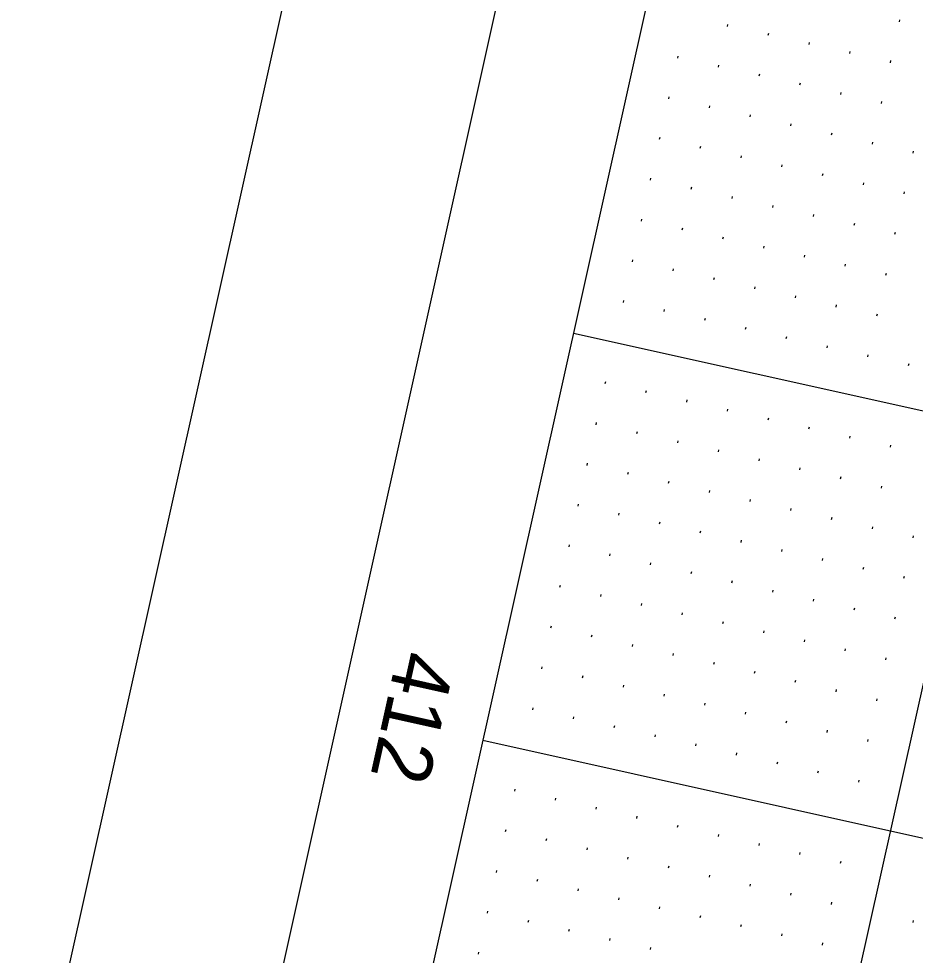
# Model space of a CAD drawing. Extents: x 2149268 to 2150830, y 142155 to 144285.
# Drawn here: x 2149611.6 to 2149719, y 143717.6 to 143829.9 of the extents above; entities that cross this region are included whole.
import ezdxf

# ---------------------------------------------------------------- set-up
doc = ezdxf.new("R2010")
doc.units = 0
for name, color, linetype in [('SHT_Plan_Profile_Sheet_Sta_Txt', 7, 'Continuous'), ('SHT_Plot_Shape_Half', 7, 'Continuous'), ('SHT_Profile_Grid_Major', 7, 'Continuous'), ('SHT_Profile_Grid_Minor', 7, 'Continuous'), ('SHT_Sheet_Border', 7, 'Continuous')]:
    doc.layers.add(name, color=color, linetype=linetype)

msp = doc.modelspace()

# ---------------------------------------------------------------- linework, layer by layer
at = {"layer": 'SHT_Plot_Shape_Half'}
msp.add_lwpolyline([(2150772.24, 143840.86), (2150403.25, 142181.39), (2149329.47, 142420.15), (2149698.47, 144079.62)], close=True, dxfattribs=at)
at = {"layer": 'SHT_Profile_Grid_Major'}
for p, q in [((2149767.6, 143964.37), (2149425.74, 142426.92)), ((2149678.09, 143792.19), (2150166.17, 143683.67)), ((2149667.24, 143743.39), (2150155.32, 143634.86))]:
    msp.add_line(p, q, dxfattribs=at)
at = {"layer": 'SHT_Profile_Grid_Minor'}
for p, q in [((2149696.56, 143829.19), (2149696.51, 143828.95)), ((2149717.17, 143829.73), (2149717.12, 143829.49)), ((2149701.44, 143828.11), (2149701.39, 143827.86)), ((2149706.32, 143827.02), (2149706.27, 143826.78)), ((2149711.21, 143825.94), (2149711.15, 143825.69)), ((2149690.6, 143825.4), (2149690.54, 143825.15)), ((2149695.48, 143824.31), (2149695.42, 143824.07)), ((2149716.09, 143824.85), (2149716.03, 143824.61)), ((2149700.36, 143823.23), (2149700.3, 143822.98)), ((2149705.24, 143822.14), (2149705.19, 143821.9)), ((2149710.12, 143821.05), (2149710.07, 143820.81)), ((2149689.51, 143820.52), (2149689.46, 143820.27)), ((2149715, 143819.97), (2149714.95, 143819.73)), ((2149694.39, 143819.43), (2149694.34, 143819.19)), ((2149699.27, 143818.34), (2149699.22, 143818.1)), ((2149704.15, 143817.26), (2149704.1, 143817.02)), ((2149688.43, 143815.63), (2149688.37, 143815.39)), ((2149709.03, 143816.17), (2149708.98, 143815.93)), ((2149693.31, 143814.55), (2149693.25, 143814.31)), ((2149713.92, 143815.09), (2149713.86, 143814.84)), ((2149698.19, 143813.46), (2149698.13, 143813.22)), ((2149718.8, 143814), (2149718.74, 143813.76)), ((2149703.07, 143812.38), (2149703.01, 143812.13)), ((2149707.95, 143811.29), (2149707.9, 143811.05)), ((2149687.34, 143810.75), (2149687.29, 143810.51)), ((2149712.83, 143810.21), (2149712.78, 143809.96)), ((2149692.22, 143809.67), (2149692.17, 143809.42)), ((2149717.71, 143809.12), (2149717.66, 143808.88)), ((2149697.1, 143808.58), (2149697.05, 143808.34)), ((2149701.98, 143807.5), (2149701.93, 143807.25)), ((2149706.86, 143806.41), (2149706.81, 143806.17)), ((2149686.26, 143805.87), (2149686.2, 143805.63)), ((2149711.75, 143805.33), (2149711.69, 143805.08)), ((2149691.14, 143804.79), (2149691.08, 143804.54)), ((2149716.63, 143804.24), (2149716.57, 143804)), ((2149696.02, 143803.7), (2149695.96, 143803.46)), ((2149700.9, 143802.62), (2149700.84, 143802.37)), ((2149685.17, 143800.99), (2149685.12, 143800.75)), ((2149705.78, 143801.53), (2149705.72, 143801.29)), ((2149690.05, 143799.91), (2149690, 143799.66)), ((2149710.66, 143800.45), (2149710.61, 143800.2)), ((2149694.93, 143798.82), (2149694.88, 143798.58)), ((2149715.54, 143799.36), (2149715.49, 143799.12)), ((2149699.81, 143797.74), (2149699.76, 143797.49)), ((2149704.69, 143796.65), (2149704.64, 143796.41)), ((2149684.09, 143796.11), (2149684.03, 143795.87)), ((2149709.57, 143795.57), (2149709.52, 143795.32)), ((2149688.97, 143795.03), (2149688.91, 143794.78)), ((2149714.46, 143794.48), (2149714.4, 143794.24)), ((2149693.85, 143793.94), (2149693.79, 143793.7)), ((2149698.73, 143792.86), (2149698.67, 143792.61)), ((2149703.61, 143791.77), (2149703.55, 143791.53)), ((2149708.49, 143790.68), (2149708.44, 143790.44)), ((2149713.37, 143789.6), (2149713.32, 143789.36)), ((2149718.25, 143788.51), (2149718.2, 143788.27)), ((2149681.91, 143786.35), (2149681.86, 143786.11)), ((2149686.8, 143785.26), (2149686.74, 143785.02)), ((2149691.68, 143784.18), (2149691.62, 143783.93)), ((2149696.56, 143783.09), (2149696.5, 143782.85)), ((2149701.44, 143782.01), (2149701.38, 143781.76)), ((2149680.83, 143781.47), (2149680.78, 143781.22)), ((2149706.32, 143780.92), (2149706.26, 143780.68)), ((2149685.71, 143780.38), (2149685.66, 143780.14)), ((2149711.2, 143779.84), (2149711.15, 143779.59)), ((2149690.59, 143779.3), (2149690.54, 143779.05)), ((2149716.08, 143778.75), (2149716.03, 143778.51)), ((2149695.47, 143778.21), (2149695.42, 143777.97)), ((2149679.74, 143776.59), (2149679.69, 143776.34)), ((2149700.35, 143777.13), (2149700.3, 143776.88)), ((2149705.23, 143776.04), (2149705.18, 143775.8)), ((2149684.63, 143775.5), (2149684.57, 143775.26)), ((2149710.11, 143774.96), (2149710.06, 143774.71)), ((2149689.51, 143774.42), (2149689.45, 143774.17)), ((2149715, 143773.87), (2149714.94, 143773.63)), ((2149694.39, 143773.33), (2149694.33, 143773.09)), ((2149678.66, 143771.71), (2149678.6, 143771.46)), ((2149699.27, 143772.25), (2149699.21, 143772)), ((2149683.54, 143770.62), (2149683.49, 143770.38)), ((2149704.15, 143771.16), (2149704.09, 143770.92)), ((2149688.42, 143769.54), (2149688.37, 143769.29)), ((2149709.03, 143770.08), (2149708.97, 143769.83)), ((2149693.3, 143768.45), (2149693.25, 143768.21)), ((2149713.91, 143768.99), (2149713.86, 143768.75)), ((2149698.18, 143767.37), (2149698.13, 143767.12)), ((2149718.79, 143767.91), (2149718.74, 143767.66)), ((2149677.57, 143766.83), (2149677.52, 143766.58)), ((2149703.06, 143766.28), (2149703.01, 143766.04)), ((2149682.45, 143765.74), (2149682.4, 143765.5)), ((2149707.94, 143765.2), (2149707.89, 143764.95)), ((2149687.34, 143764.66), (2149687.28, 143764.41)), ((2149712.82, 143764.11), (2149712.77, 143763.87)), ((2149692.22, 143763.57), (2149692.16, 143763.33)), ((2149717.71, 143763.03), (2149717.65, 143762.78)), ((2149676.49, 143761.95), (2149676.43, 143761.7)), ((2149697.1, 143762.49), (2149697.04, 143762.24)), ((2149681.37, 143760.86), (2149681.31, 143760.62)), ((2149701.98, 143761.4), (2149701.92, 143761.16)), ((2149686.25, 143759.78), (2149686.2, 143759.53)), ((2149706.86, 143760.31), (2149706.8, 143760.07)), ((2149711.74, 143759.23), (2149711.68, 143758.99)), ((2149691.13, 143758.69), (2149691.08, 143758.45)), ((2149716.62, 143758.14), (2149716.57, 143757.9)), ((2149675.4, 143757.06), (2149675.35, 143756.82)), ((2149696.01, 143757.6), (2149695.96, 143757.36)), ((2149680.28, 143755.98), (2149680.23, 143755.74)), ((2149700.89, 143756.52), (2149700.84, 143756.28)), ((2149685.16, 143754.89), (2149685.11, 143754.65)), ((2149705.77, 143755.43), (2149705.72, 143755.19)), ((2149690.05, 143753.81), (2149689.99, 143753.56)), ((2149710.65, 143754.35), (2149710.6, 143754.1)), ((2149694.93, 143752.72), (2149694.87, 143752.48)), ((2149715.53, 143753.26), (2149715.48, 143753.02)), ((2149674.32, 143752.18), (2149674.26, 143751.94)), ((2149699.81, 143751.64), (2149699.75, 143751.39)), ((2149679.2, 143751.1), (2149679.14, 143750.85)), ((2149704.69, 143750.55), (2149704.63, 143750.31)), ((2149684.08, 143750.01), (2149684.03, 143749.77)), ((2149709.57, 143749.47), (2149709.51, 143749.22)), ((2149688.96, 143748.93), (2149688.91, 143748.68)), ((2149714.45, 143748.38), (2149714.4, 143748.14)), ((2149673.23, 143747.3), (2149673.18, 143747.06)), ((2149693.84, 143747.84), (2149693.79, 143747.6)), ((2149678.11, 143746.22), (2149678.06, 143745.97)), ((2149698.72, 143746.76), (2149698.67, 143746.51)), ((2149682.99, 143745.13), (2149682.94, 143744.89)), ((2149703.6, 143745.67), (2149703.55, 143745.43)), ((2149687.87, 143744.05), (2149687.82, 143743.8)), ((2149708.48, 143744.59), (2149708.43, 143744.34)), ((2149713.36, 143743.5), (2149713.31, 143743.26)), ((2149692.76, 143742.96), (2149692.7, 143742.72)), ((2149697.64, 143741.88), (2149697.58, 143741.63)), ((2149702.52, 143740.79), (2149702.46, 143740.55)), ((2149707.4, 143739.71), (2149707.34, 143739.46)), ((2149712.28, 143738.62), (2149712.22, 143738.38)), ((2149671.06, 143737.54), (2149671.01, 143737.3)), ((2149675.94, 143736.46), (2149675.89, 143736.21)), ((2149680.82, 143735.37), (2149680.77, 143735.13)), ((2149685.7, 143734.29), (2149685.65, 143734.04)), ((2149669.98, 143732.66), (2149669.92, 143732.42)), ((2149690.59, 143733.2), (2149690.53, 143732.96)), ((2149674.86, 143731.58), (2149674.8, 143731.33)), ((2149695.47, 143732.12), (2149695.41, 143731.87)), ((2149679.74, 143730.49), (2149679.68, 143730.25)), ((2149700.35, 143731.03), (2149700.29, 143730.79)), ((2149684.62, 143729.4), (2149684.56, 143729.16)), ((2149705.23, 143729.94), (2149705.17, 143729.7)), ((2149668.89, 143727.78), (2149668.84, 143727.54)), ((2149689.5, 143728.32), (2149689.45, 143728.08)), ((2149710.11, 143728.86), (2149710.05, 143728.62)), ((2149673.77, 143726.69), (2149673.72, 143726.45)), ((2149694.38, 143727.23), (2149694.33, 143726.99)), ((2149678.65, 143725.61), (2149678.6, 143725.37)), ((2149699.26, 143726.15), (2149699.21, 143725.91)), ((2149683.53, 143724.52), (2149683.48, 143724.28)), ((2149704.14, 143725.06), (2149704.09, 143724.82)), ((2149688.41, 143723.44), (2149688.36, 143723.19)), ((2149709.02, 143723.98), (2149708.97, 143723.73)), ((2149667.81, 143722.9), (2149667.75, 143722.66)), ((2149693.3, 143722.35), (2149693.24, 143722.11)), ((2149672.69, 143721.81), (2149672.63, 143721.57)), ((2149698.18, 143721.27), (2149698.12, 143721.02)), ((2149718.78, 143721.81), (2149718.73, 143721.56)), ((2149677.57, 143720.73), (2149677.51, 143720.48)), ((2149703.06, 143720.18), (2149703, 143719.94)), ((2149682.45, 143719.64), (2149682.39, 143719.4)), ((2149707.94, 143719.1), (2149707.88, 143718.85)), ((2149666.72, 143718.02), (2149666.67, 143717.77)), ((2149687.33, 143718.56), (2149687.28, 143718.31))]:
    msp.add_line(p, q, dxfattribs=at)
at = {"layer": 'SHT_Sheet_Border'}
msp.add_line((2149718.79, 143975.22), (2149433.9, 142694.01), dxfattribs=at)
msp.add_lwpolyline([(2150726.67, 143751.11), (2150384.81, 142213.66), (2149359.84, 142441.57), (2149701.71, 143979.02)], close=True, dxfattribs=at)

# ---------------------------------------------------------------- texts
at = {"layer": 'SHT_Plan_Profile_Sheet_Sta_Txt'}
msp.add_text('412', height=7, rotation=257.4638, dxfattribs=at).set_placement((2149657.14, 143754.42))

doc.saveas('drawing.dxf')
